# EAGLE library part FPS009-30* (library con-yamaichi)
SD Card and MMC Reader (Manual Insertion) Source: http://www.yamaichi.de/pdf/c_fps009_3000.pdf
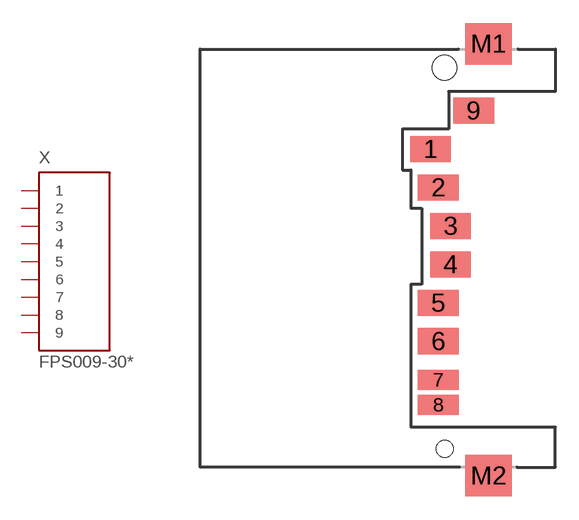
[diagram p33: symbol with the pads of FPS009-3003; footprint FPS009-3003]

Designator prefix X

## FPS009-30003 (MPN: FPS009-3003-BL; OC_FARNELL: 1143953; OC_NEWARK: 91K9876), FPS009-30005 (OC_FARNELL: unknown; OC_NEWARK: unknown)  [FPS009-3003]
1  1  in
2  2  in
3  3  in
4  4  in
5  5  in
6  6  in
7  7  in
8  8  in
9  9  in

## Footprint FPS009-3003 (pad centres in mm)
SD Card and MMC Reader (Manual Insertion) Source: http://www.yamaichi.de/pdf/c_fps009_3000.pdf
smd 2.65 x 1.7: 1 -0.915,-5.3; 2 -0.415,-7.8; 3 0.385,-10.3; 4 0.385,-12.8; 5 -0.415,-15.3; 6 -0.415,-17.8; 9 1.885,-2.8
smd 2.65 x 1.3: 7 -0.415,-20.3; 8 -0.415,-21.925
smd 3 x 2.7: M1 2.85,1.55; M2 2.85,-26.55
hole 1.6 at 0,0
hole 1.1 at 0,-24.8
